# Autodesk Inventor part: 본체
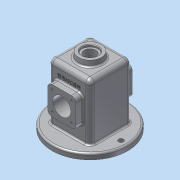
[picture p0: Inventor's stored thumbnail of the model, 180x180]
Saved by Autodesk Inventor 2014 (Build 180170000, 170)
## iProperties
Created: 2021-08
Part Number: 본체
Material: 알루미늄 6061
Document SubType Name: Modeling
Designer: dg
Density: 2.71 g/cm^3
Appearance: 알루미늄 - 평지
Mass: 823.388 g
Surface Area: 950.132 cm^2
Volume: 303.833 cm^3
Author: dg
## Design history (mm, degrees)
sketch "스케치1"
  geometry: L1 (37, -37)-(-37, -37); L2 (-37, -37)-(-37, 37); L3 (-37, 37)-(37, 37); L4 (37, 37)-(37, -37); L5 (37, -37)-(-37, 37); L6 (-37, -37)-(37, 37); 1 further point
  constraints: 12 end point, 2 midpoint, 2 parallel, 1 horizontal, 1 perpendicular
  dimensions: "d0" = 74 distance of L2.end L3.end; "d1" = 74 distance of L3.end L1.start
extrude "돌출1" new body sketch "스케치1" stored distance "d2" = 100; taper "d3" = 0 deg
node "작업 평면1"
sketch "스케치2"
  geometry: C1 r 67 at (0, 0); 1 further point
  constraints: 1 centre point, 1 coincident
  dimensions: "d5" = 134 diameter of C1
extrude "돌출2" join sketch "스케치2" distance "d6" = 10; taper "d7" = 0 deg
sketch "스케치3" dims "d8" = 110
  geometry: L1 (37, -37)-(-37, -37) reference; L2 (0, 0)-(0, 55); C1 r 67 at (0, 0) reference; C2 r 4.5 at (0, 55)
  constraints: 2 coincident, 2 end point, 1 centre point, 1 perpendicular, 1 vertical alignment, 2 other
  dimensions: "d9" = 9 diameter of C2
extrude "돌출3" cut sketch "스케치3" stored distance "d10" = 10; taper "d11" = 0 deg
fillet "모깎기1" dims "d12" = 3
fillet "모깎기2" dims "d13" = 8
sketch "스케치4"
  geometry: C1 r 20 at (0, 0); 1 further point
  constraints: 1 centre point, 1 coincident
  dimensions: "d14" = 40 diameter of C1
extrude "돌출4" join sketch "스케치4" distance "d15" = 10; taper "d16" = 0 deg
sketch "스케치5"
  geometry: L1 (-32, -32)-(32, -32); L2 (32, -32)-(32, 32); L3 (32, 32)-(-32, 32); L4 (-32, 32)-(-32, -32); L5 (-32, -32)-(32, 32); L6 (32, -32)-(-32, 32); C1 r 67 at (0, 0) reference
  constraints: 12 end point, 2 midpoint, 2 parallel, 1 horizontal, 1 perpendicular
  dimensions: "d17" = 64 distance of L2.end L3.end; "d18" = 64 distance of L1.end L2.end
extrude "돌출5" cut sketch "스케치5" distance "d19" = 105; taper "d20" = 0 deg
sketch "스케치6"
  geometry: C1 r 20 at (0, 0) reference; C2 r 14 at (0, 0)
  constraints: 1 centre point, 1 coincident
  dimensions: "d22" = 28 diameter of C2
extrude "돌출6" cut sketch "스케치6" distance "d23" = 4; taper "d24" = 0 deg
sketch "스케치7"
  geometry: C1 r 14 at (0, 0) reference; C2 r 10.5 at (0, 0)
  constraints: 1 centre point, 1 coincident
  dimensions: "d25" = 21 diameter of C2
extrude "돌출7" cut sketch "스케치7" stored distance "d26" = 4; taper "d27" = 0 deg
sketch "스케치8"
  geometry: L1 (67, 54)-(17, 54); L2 (17, 54)-(17, 4); L3 (17, 4)-(67, 4); L4 (67, 4)-(67, 54); L5 (67, 54)-(17, 4); L6 (17, 54)-(67, 4); 1 further point
  constraints: 12 end point, 2 midpoint, 2 parallel, 1 horizontal, 1 perpendicular
  dimensions: "d29" = 50 distance of L1.end L2.end; "d30" = 50 distance of L1.start L1.end
extrude "돌출8" join sketch "스케치8" distance "d31" = 13; taper "d32" = 0 deg
sketch "스케치9"
  geometry: C1 r 16 at (42, 29); 1 further point
  constraints: 1 centre point, 1 coincident
  dimensions: "d33" = 32 diameter of C1
extrude "돌출9" cut sketch "스케치9" stored distance "d34" = 13; taper "d35" = 0 deg
fillet "모깎기5" dims "d36" = 8
fillet "모깎기6" dims "d37" = 3
sketch "스케치10"
  geometry: L1 (59, 12)-(25, 12); L2 (25, 12)-(25, 46); L3 (25, 46)-(59, 46); L4 (59, 46)-(59, 12); L5 (59, 12)-(25, 46); L6 (25, 12)-(59, 46); C1 r 16 at (42, 29) reference; 1 further point
  constraints: 12 end point, 2 midpoint, 2 parallel, 1 coincident, 1 horizontal, 1 perpendicular
  dimensions: "d38" = 34 distance of L1.end L2.end; "d39" = 34 distance of L2.end L3.end
hole "구멍1" sketch "스케치10" at (25, 12) diameter "d40" = 3.242; stored, may be unused: countersink angle "d44" = 90 deg, drill point angle "d46" = 118 deg; dims "d41" = 8, "d42" = 4, "d43" = 2, "d45" = 10
sketch "스케치11"
  geometry: L1 (-32, -60)-(-32, 45) reference; L2 (-50, -16)-(-50, 16) reference; L3 (0, 0)-(-50, 0); L4 (-32, -25)-(-25, -22.452); L5 (-25, -22.452)-(-25, -16); L6 (-50, -16)-(-32, -16) reference; L7 (-25, -16)-(-32, -16)
  constraints: 8 end point, 1 collinear, 1 midpoint, 1 perpendicular, 1 point on line
  dimensions: "d53" = 110 deg angle of L1 L4; "d54" = 7 distance between parallel lines of L1 L5; "d55" = 50 diameter of L4.start L3
revolve "회전1" sketch "스케치11" stored, may be unused: angle "d56" = 90 deg
fillet "모깎기7" dims "d57" = 3
fillet "모깎기8" dims "d58" = 3
sketch "스케치12"
  geometry: L1 (-18, 49)-(-18, 9) reference; 2 further points
  constraints: 1 horizontal alignment, 1 other
  dimensions: "d59" = 28 distance from line of point (10, 29) L1
extrude "돌출10" join sketch "스케치12" distance "d60" = 0.5; taper "d61" = 0 deg
sketch "스케치13"
  geometry: L1 (-29, 50)-(29, 50) reference; L2 (37, 42)-(37, -47) reference; L3 (20, 50)-(20, 60) reference; L4 (20, 60)-(-20, 60) reference; L5 (20, 60)-(21.051, 50); L6 (0, 60)-(0, 0); L7 (21.051, 50)-(20, 50); L8 (20, 60)-(20, 50); A1 r 8 centre (29, 42) between (37, 42) and (29, 50) reference
  constraints: 8 end point, 3 perpendicular, 2 point on line, 1 midpoint
  dimensions: "d62" = 6 deg angle of L5 L2
revolve "회전2" sketch "스케치13" stored, may be unused: angle "d63" = 90 deg
fillet "모깎기9" dims "d64" = 3
chamfer "모따기1" distance "d65" = 1; stored, may be unused: second distance "d66" = 2, angle "d67" = 45 deg
node "솔리드1"
mirror "대칭1"
pattern_linear "직사각형 패턴1" dims "d49" = 34, "d52" = 34
mirror "대칭2"
